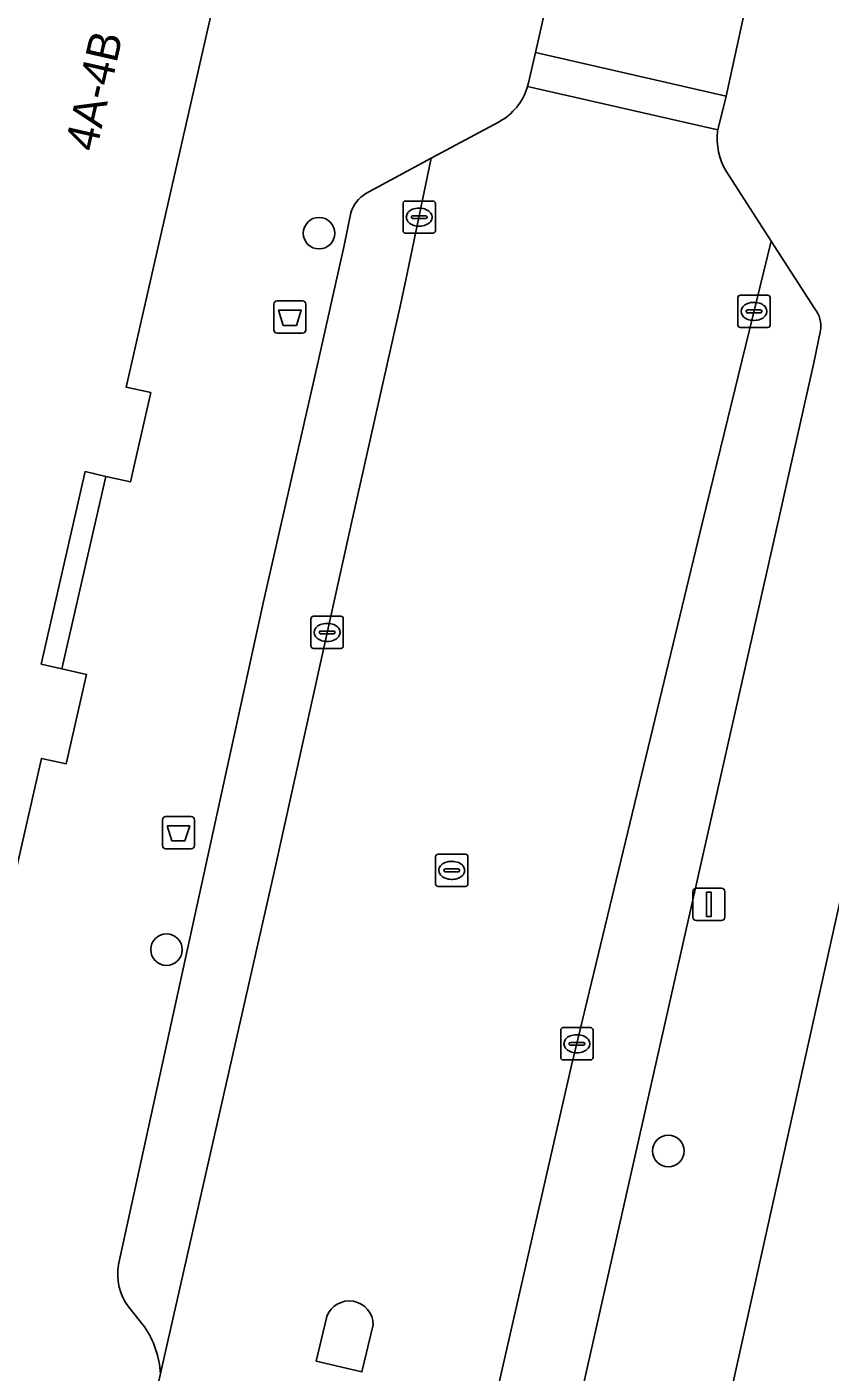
# Model space of a CAD drawing. Extents: x 161771 to 163125, y 382475 to 383179.
# Drawn here: x 162488.21 to 162513.11, y 382775.57 to 382817.29 of the extents above; entities that cross this region are included whole.
import ezdxf

# ---------------------------------------------------------------- set-up
doc = ezdxf.new("R2010")
doc.units = 0
for name, color, linetype in [('IMGEO_Afvalbak', 7, 'Continuous'), ('IMGEO_Boom', 7, 'Continuous'), ('IMGEO_Erf', 7, 'Continuous'), ('IMGEO_Kolk', 7, 'Continuous'), ('IMGEO_Lichtmast', 7, 'Continuous'), ('IMGEO_Pand', 7, 'Continuous'), ('IMGEO_Pand_nummerreeks', 7, 'Continuous'), ('IMGEO_Parkeervlak_open', 7, 'Continuous'), ('IMGEO_Rijbaan_lokaal_open', 7, 'Continuous'), ('IMGEO_Rioolput', 7, 'Continuous'), ('IMGEO_Verkeerseiland_gesloten', 7, 'Continuous'), ('IMGEO_Voetpad_open', 7, 'Continuous')]:
    doc.layers.add(name, color=color, linetype=linetype)

msp = doc.modelspace()

# ---------------------------------------------------------------- linework, layer by layer
at = {"layer": 'IMGEO_Afvalbak'}
for p, q in [((162495.868, 382807.886), (162495.868, 382808.686)), ((162495.868, 382808.686), (162495.868, 382807.886)), ((162495.968, 382808.786), (162496.758, 382808.786)), ((162496.758, 382808.786), (162495.968, 382808.786)), ((162496.858, 382808.686), (162496.858, 382807.886)), ((162496.858, 382807.886), (162496.858, 382808.686)), ((162496.758, 382807.786), (162495.968, 382807.786)), ((162495.968, 382807.786), (162496.758, 382807.786)), ((162492.414, 382791.895), (162492.414, 382792.695)), ((162492.414, 382792.695), (162492.414, 382791.895)), ((162492.514, 382792.795), (162493.304, 382792.795)), ((162493.304, 382792.795), (162492.514, 382792.795)), ((162493.404, 382792.695), (162493.404, 382791.895)), ((162493.404, 382791.895), (162493.404, 382792.695)), ((162493.304, 382791.795), (162492.514, 382791.795)), ((162492.514, 382791.795), (162493.304, 382791.795))]:
    msp.add_line(p, q, dxfattribs=at)
for points in [[(162496.011, 382808.5), (162496.715, 382808.5), (162496.566, 382808.03), (162496.16, 382808.03), (162496.011, 382808.5)], [(162492.557, 382792.509), (162493.261, 382792.509), (162493.112, 382792.039), (162492.706, 382792.039), (162492.557, 382792.509)]]:
    msp.add_lwpolyline(points, dxfattribs=at)
for centre, start, end in [((162495.968, 382808.686), 90, 180), ((162495.968, 382808.686), 90, 180), ((162496.758, 382808.686), 0, 90), ((162496.758, 382808.686), 360, 90), ((162495.968, 382807.886), 180, 270), ((162495.968, 382807.886), 180, 270), ((162496.758, 382807.886), 270, 0), ((162496.758, 382807.886), 270, 0), ((162492.514, 382792.695), 90, 180), ((162492.514, 382792.695), 90, 180), ((162493.304, 382792.695), 0, 90), ((162493.304, 382792.695), 360, 90), ((162492.514, 382791.895), 180, 270), ((162492.514, 382791.895), 180, 270), ((162493.304, 382791.895), 270, 0), ((162493.304, 382791.895), 270, 0)]:
    msp.add_arc(centre, 0.1, start, end, dxfattribs=at)
at = {"layer": 'IMGEO_Boom'}
for centre in [(162497.269, 382810.889), (162492.54, 382788.668), (162508.091, 382782.426)]:
    msp.add_circle(centre, 0.489, dxfattribs=at)
at = {"layer": 'IMGEO_Erf'}
msp.add_lwpolyline([(162516.107, 382774.679), (162516.72, 382777.452), (162517.354, 382780.316), (162516.872, 382780.422), (162517.638, 382783.886), (162518.434, 382787.483), (162518.947, 382787.369), (162519.547, 382790.08), (162520.181, 382792.947), (162519.663, 382793.062), (162520.436, 382796.553), (162521.242, 382800.197), (162521.832, 382800.066), (162522.427, 382802.759), (162523.068, 382805.656), (162522.524, 382805.776), (162523.312, 382809.334), (162523.399, 382809.647), (162524.848, 382809.317), (162526.114, 382815.089), (162519.291, 382816.631), (162509.13, 382770.881)], dxfattribs=at)
at = {"layer": 'IMGEO_Kolk'}
for p, q in [((162499.871, 382810.961), (162499.871, 382811.813)), ((162499.946, 382811.887), (162500.798, 382811.887)), ((162500.359, 382811.667), (162500.384, 382811.667)), ((162500.872, 382811.813), (162500.872, 382810.961)), ((162500.13, 382811.381), (162500.13, 382811.393)), ((162500.568, 382811.344), (162500.17, 382811.344)), ((162500.173, 382811.43), (162500.571, 382811.43)), ((162500.614, 382811.393), (162500.614, 382811.381)), ((162500.798, 382810.887), (162499.946, 382810.887)), ((162500.382, 382811.107), (162500.357, 382811.107)), ((162510.248, 382808.038), (162510.248, 382808.89)), ((162510.323, 382808.964), (162511.175, 382808.964)), ((162510.736, 382808.744), (162510.761, 382808.744)), ((162511.249, 382808.89), (162511.249, 382808.038)), ((162510.507, 382808.458), (162510.507, 382808.47)), ((162510.945, 382808.421), (162510.547, 382808.421)), ((162510.55, 382808.507), (162510.948, 382808.507)), ((162510.991, 382808.47), (162510.991, 382808.458)), ((162511.175, 382807.964), (162510.323, 382807.964)), ((162510.759, 382808.184), (162510.734, 382808.184)), ((162497.018, 382798.082), (162497.018, 382798.934)), ((162497.093, 382799.008), (162497.945, 382799.008)), ((162497.506, 382798.788), (162497.531, 382798.788)), ((162498.019, 382798.934), (162498.019, 382798.082)), ((162497.277, 382798.502), (162497.277, 382798.514)), ((162497.715, 382798.465), (162497.317, 382798.465)), ((162497.32, 382798.551), (162497.718, 382798.551)), ((162497.761, 382798.514), (162497.761, 382798.502)), ((162497.945, 382798.008), (162497.093, 382798.008)), ((162497.529, 382798.228), (162497.504, 382798.228)), ((162504.758, 382785.324), (162504.758, 382786.176)), ((162504.833, 382786.25), (162505.685, 382786.25)), ((162505.759, 382786.176), (162505.759, 382785.324)), ((162505.017, 382785.744), (162505.017, 382785.756)), ((162505.06, 382785.793), (162505.458, 382785.793)), ((162505.246, 382786.03), (162505.271, 382786.03)), ((162505.501, 382785.756), (162505.501, 382785.744)), ((162505.455, 382785.707), (162505.057, 382785.707)), ((162505.269, 382785.47), (162505.244, 382785.47)), ((162505.685, 382785.25), (162504.833, 382785.25))]:
    msp.add_line(p, q, dxfattribs=at)
for points in [[(162499.871, 382810.961), (162499.871, 382811.813)], [(162499.946, 382811.887), (162500.798, 382811.887)], [(162500.872, 382811.813), (162500.872, 382810.961)], [(162500.798, 382810.887), (162499.946, 382810.887)], [(162510.248, 382808.038), (162510.248, 382808.89)], [(162510.323, 382808.964), (162511.175, 382808.964)], [(162511.249, 382808.89), (162511.249, 382808.038)], [(162511.175, 382807.964), (162510.323, 382807.964)], [(162497.018, 382798.082), (162497.018, 382798.934)], [(162497.093, 382799.008), (162497.945, 382799.008)], [(162498.019, 382798.934), (162498.019, 382798.082)], [(162497.945, 382798.008), (162497.093, 382798.008)], [(162504.758, 382785.324), (162504.758, 382786.176)], [(162504.833, 382786.25), (162505.685, 382786.25)], [(162505.759, 382786.176), (162505.759, 382785.324)], [(162505.685, 382785.25), (162504.833, 382785.25)]]:
    msp.add_lwpolyline(points, dxfattribs=at)
for centre, radius, start, end in [((162499.948, 382811.811), 0.0765, 91.552, 178.448), ((162499.948, 382811.811), 0.0765, 91.552, 178.448), ((162500.796, 382811.811), 0.0765, 1.552, 88.448), ((162500.796, 382811.811), 0.0765, 1.552, 88.448), ((162500.17, 382811.39), 0.0403, 85.8775, 175.7526), ((162500.167, 382811.38), 0.0366, 178.938, 274.7102), ((162500.571, 382811.387), 0.043, 264.8664, 352.4533), ((162500.575, 382811.392), 0.0386, 1.7309, 96.639), ((162499.948, 382810.963), 0.0765, 181.552, 268.448), ((162499.948, 382810.963), 0.0765, 181.552, 268.448), ((162500.796, 382810.963), 0.0765, 271.552, 358.448), ((162500.796, 382810.963), 0.0765, 271.552, 358.448), ((162510.325, 382808.888), 0.0765, 91.552, 178.448), ((162510.325, 382808.888), 0.0765, 91.552, 178.448), ((162511.173, 382808.888), 0.0765, 1.552, 88.448), ((162511.173, 382808.888), 0.0765, 1.552, 88.448), ((162510.547, 382808.467), 0.0403, 85.8775, 175.7526), ((162510.544, 382808.457), 0.0366, 178.938, 274.7102), ((162510.948, 382808.464), 0.043, 264.8664, 352.4533), ((162510.952, 382808.469), 0.0386, 1.7309, 96.639), ((162510.325, 382808.04), 0.0765, 181.552, 268.448), ((162510.325, 382808.04), 0.0765, 181.552, 268.448), ((162511.173, 382808.04), 0.0765, 271.552, 358.448), ((162511.173, 382808.04), 0.0765, 271.552, 358.448), ((162497.095, 382798.932), 0.0765, 91.552, 178.448), ((162497.095, 382798.932), 0.0765, 91.552, 178.448), ((162497.943, 382798.932), 0.0765, 1.552, 88.448), ((162497.943, 382798.932), 0.0765, 1.552, 88.448), ((162497.317, 382798.511), 0.0403, 85.8775, 175.7526), ((162497.314, 382798.501), 0.0366, 178.938, 274.7102), ((162497.718, 382798.508), 0.043, 264.8664, 352.4533), ((162497.722, 382798.513), 0.0386, 1.7309, 96.639), ((162497.095, 382798.084), 0.0765, 181.552, 268.448), ((162497.095, 382798.084), 0.0765, 181.552, 268.448), ((162497.943, 382798.084), 0.0765, 271.552, 358.448), ((162497.943, 382798.084), 0.0765, 271.552, 358.448), ((162504.835, 382786.174), 0.0765, 91.552, 178.448), ((162504.835, 382786.174), 0.0765, 91.552, 178.448), ((162505.683, 382786.174), 0.0765, 1.552, 88.448), ((162505.683, 382786.174), 0.0765, 1.552, 88.448), ((162505.057, 382785.753), 0.0403, 85.8775, 175.7526), ((162505.054, 382785.743), 0.0366, 178.938, 274.7102), ((162505.458, 382785.75), 0.043, 264.8664, 352.4533), ((162505.462, 382785.755), 0.0386, 1.7309, 96.639), ((162504.835, 382785.326), 0.0765, 181.552, 268.448), ((162504.835, 382785.326), 0.0765, 181.552, 268.448), ((162505.683, 382785.326), 0.0765, 271.552, 358.448), ((162505.683, 382785.326), 0.0765, 271.552, 358.448)]:
    msp.add_arc(centre, radius, start, end, dxfattribs=at)
for centre, major_axis, ratio, start_param, end_param in [((162500.358, 382811.387), (-0.387, 0.002), 0.722429, 4.712389, 7.853982), ((162500.383, 382811.387), (-0.39, 0.002), 0.717154, 1.570796, 4.712389), ((162510.735, 382808.464), (-0.387, 0.002), 0.722429, 4.712389, 7.853982), ((162510.76, 382808.464), (-0.39, 0.002), 0.717154, 1.570796, 4.712389), ((162497.505, 382798.508), (-0.387, 0.002), 0.722429, 4.712389, 7.853982), ((162497.53, 382798.508), (-0.39, 0.002), 0.717154, 1.570796, 4.712389), ((162505.245, 382785.75), (-0.387, 0.002), 0.722429, 4.712389, 7.853982), ((162505.27, 382785.75), (-0.39, 0.002), 0.717154, 1.570796, 4.712389)]:
    msp.add_ellipse(centre, major_axis=major_axis, ratio=ratio, start_param=start_param, end_param=end_param, dxfattribs=at)
at = {"layer": 'IMGEO_Lichtmast'}
for p, q in [((162508.855, 382789.674), (162508.855, 382790.474)), ((162508.855, 382790.474), (162508.855, 382789.674)), ((162508.955, 382790.574), (162509.745, 382790.574)), ((162509.745, 382790.574), (162508.955, 382790.574)), ((162509.845, 382790.474), (162509.845, 382789.674)), ((162509.845, 382789.674), (162509.845, 382790.474)), ((162509.745, 382789.574), (162508.955, 382789.574)), ((162508.955, 382789.574), (162509.745, 382789.574))]:
    msp.add_line(p, q, dxfattribs=at)
msp.add_lwpolyline([(162509.275, 382790.449), (162509.425, 382790.449), (162509.425, 382789.699), (162509.275, 382789.699), (162509.275, 382790.449)], dxfattribs=at)
for centre, start, end in [((162508.955, 382790.474), 90, 180), ((162508.955, 382790.474), 90, 180), ((162509.745, 382790.474), 0, 90), ((162509.745, 382790.474), 360, 90), ((162508.955, 382789.674), 180, 270), ((162508.955, 382789.674), 180, 270), ((162509.745, 382789.674), 270, 0), ((162509.745, 382789.674), 270, 0)]:
    msp.add_arc(centre, 0.1, start, end, dxfattribs=at)
at = {"layer": 'IMGEO_Pand'}
msp.add_lwpolyline([(162484.441, 382776.066), (162488.665, 382794.601), (162489.427, 382794.428), (162490.06, 382797.207), (162489.299, 382797.38), (162488.656, 382797.527), (162490.016, 382803.494), (162490.658, 382803.348), (162491.42, 382803.174), (162492.051, 382805.943), (162491.289, 382806.116), (162494.91, 382822.004)], dxfattribs=at)
at = {"layer": 'IMGEO_Parkeervlak_open'}
for points in [[(162498.249, 382801.811), (162499.796, 382808.668), (162500, 382809.643), (162500.747, 382813.211), (162498.715, 382812.115)], [(162498.254, 382811.521), (162498.045, 382810.505), (162497.218, 382806.814), (162495.55, 382799.47), (162491.057, 382778.902)], [(162512.632, 382808.546), (162511.28, 382810.646), (162509.154, 382801.926), (162505.086, 382785.036), (162500.442, 382764.689), (162500, 382762.664), (162498.277, 382754.772), (162497.178, 382750), (162496.887, 382748.736), (162496.008, 382745.127), (162493.813, 382737.211), (162492.079, 382731.423), (162488.748, 382721.634), (162487.266, 382717.521), (162483.52, 382707.553), (162479.897, 382698.492), (162476.717, 382691.181), (162472.466, 382682.195), (162468.158, 382672.932), (162463.316, 382663.492), (162458.673, 382655.168), (162454.89, 382648.901), (162451.763, 382643.729), (162451.23, 382642.792)], [(162511.434, 382801.667), (162512.601, 382806.873), (162512.805, 382807.873)], [(162492.352, 382775.519), (162495.881, 382791.077), (162498.249, 382801.811)], [(162502.562, 382762.312), (162511.434, 382801.667)], [(162491.372, 382777.577), (162491.859, 382776.975)]]:
    msp.add_lwpolyline(points, dxfattribs=at)
for centre, radius, start, end in [((162499.234, 382811.237), 1.02, 120.5559, 163.8144), ((162511.994, 382808.023), 0.825, 349.5131, 39.3193), ((162492.695, 382778.591), 1.667, 169.2655, 217.4805), ((162489.461, 382775.352), 2.895, 3.3117, 34.1004)]:
    msp.add_arc(centre, radius, start, end, dxfattribs=at)
at = {"layer": 'IMGEO_Rijbaan_lokaal_open'}
for points in [[(162505.365, 382822.78), (162505.223, 382822.13), (162504.743, 382819.885), (162503.973, 382816.498), (162509.884, 382815.143), (162510.621, 382818.519), (162511.296, 382821.626), (162511.992, 382824.866)], [(162509.615, 382814.051), (162509.625, 382814.094), (162503.728, 382815.434)], [(162502.847, 382814.344), (162500.747, 382813.211), (162500, 382809.643), (162499.796, 382808.668), (162498.249, 382801.811), (162495.881, 382791.077), (162492.352, 382775.519), (162492.248, 382775.059), (162492.168, 382774.731), (162491.965, 382773.425), (162487.236, 382754.153), (162486.921, 382753.008), (162486.326, 382750.841), (162486.109, 382750), (162485.939, 382749.34), (162483.311, 382740.485), (162480.535, 382731.373)], [(162509.154, 382801.926), (162511.28, 382810.646), (162509.883, 382812.817)], [(162468.158, 382672.932), (162472.466, 382682.195), (162476.717, 382691.181), (162479.897, 382698.492), (162483.52, 382707.553), (162487.266, 382717.521), (162488.748, 382721.634), (162492.079, 382731.423), (162493.813, 382737.211), (162496.008, 382745.127), (162496.887, 382748.736), (162497.178, 382750), (162498.277, 382754.772), (162500, 382762.664), (162500.442, 382764.689), (162505.086, 382785.036), (162509.154, 382801.926)], [(162498.596, 382775.571), (162497.178, 382775.911), (162497.508, 382777.289)], [(162498.948, 382777.038), (162498.596, 382775.571)]]:
    msp.add_lwpolyline(points, dxfattribs=at)
msp.add_lwpolyline([(162503.973, 382816.498), (162503.758, 382815.55), (162503.728, 382815.434), (162509.625, 382814.094), (162509.884, 382815.143)], close=True, dxfattribs=at)
for centre, radius, start, end in [((162501.973, 382815.952), 1.83, 298.5364, 343.5694), ((162511.646, 382813.846), 2.041, 174.2369, 210.2695), ((162498.205, 382777.032), 0.743, 0.469, 159.7558)]:
    msp.add_arc(centre, radius, start, end, dxfattribs=at)
at = {"layer": 'IMGEO_Rioolput'}
for p, q in [((162500.956, 382791.628), (162501.808, 382791.628)), ((162500.881, 382790.702), (162500.881, 382791.554)), ((162501.183, 382791.171), (162501.581, 382791.171)), ((162501.369, 382791.408), (162501.394, 382791.408)), ((162501.882, 382791.554), (162501.882, 382790.702)), ((162501.14, 382791.122), (162501.14, 382791.134)), ((162501.578, 382791.085), (162501.18, 382791.085)), ((162501.392, 382790.848), (162501.367, 382790.848)), ((162501.624, 382791.134), (162501.624, 382791.122)), ((162501.808, 382790.628), (162500.956, 382790.628))]:
    msp.add_line(p, q, dxfattribs=at)
for points in [[(162500.956, 382791.628), (162501.808, 382791.628)], [(162500.881, 382790.702), (162500.881, 382791.554)], [(162501.882, 382791.554), (162501.882, 382790.702)], [(162501.808, 382790.628), (162500.956, 382790.628)]]:
    msp.add_lwpolyline(points, dxfattribs=at)
for centre, radius, start, end in [((162500.958, 382791.552), 0.0765, 91.552, 178.448), ((162500.958, 382791.552), 0.0765, 91.552, 178.448), ((162501.806, 382791.552), 0.0765, 1.552, 88.448), ((162501.806, 382791.552), 0.0765, 1.552, 88.448), ((162501.18, 382791.131), 0.0403, 85.8775, 175.7526), ((162501.585, 382791.133), 0.0386, 1.7309, 96.639), ((162501.177, 382791.121), 0.0366, 178.938, 274.7102), ((162501.581, 382791.128), 0.043, 264.8664, 352.4533), ((162500.958, 382790.704), 0.0765, 181.552, 268.448), ((162500.958, 382790.704), 0.0765, 181.552, 268.448), ((162501.806, 382790.704), 0.0765, 271.552, 358.448), ((162501.806, 382790.704), 0.0765, 271.552, 358.448)]:
    msp.add_arc(centre, radius, start, end, dxfattribs=at)
for centre, major_axis, ratio, start_param, end_param in [((162501.368, 382791.128), (-0.387, 0.002), 0.722429, 4.712389, 7.853982), ((162501.393, 382791.128), (-0.39, 0.002), 0.717154, 1.570796, 4.712389)]:
    msp.add_ellipse(centre, major_axis=major_axis, ratio=ratio, start_param=start_param, end_param=end_param, dxfattribs=at)
at = {"layer": 'IMGEO_Verkeerseiland_gesloten'}
msp.add_lwpolyline([(162497.508, 382777.289), (162497.178, 382775.911), (162498.596, 382775.571), (162498.948, 382777.038)], dxfattribs=at)
msp.add_arc((162498.205, 382777.032), 0.743, 0.469, 159.7558, dxfattribs=at)
at = {"layer": 'IMGEO_Voetpad_open'}
for points in [[(162503.728, 382815.434), (162503.758, 382815.55), (162503.973, 382816.498), (162504.743, 382819.885), (162494.91, 382822.004), (162491.289, 382806.116), (162492.051, 382805.943), (162491.42, 382803.174), (162490.658, 382803.348), (162489.299, 382797.38), (162490.06, 382797.207), (162489.427, 382794.428), (162488.665, 382794.601), (162484.441, 382776.066), (162483.267, 382770.618), (162485.023, 382770.227)], [(162519.291, 382816.631), (162510.621, 382818.519), (162509.884, 382815.143), (162509.625, 382814.094), (162509.615, 382814.051)], [(162472.565, 382660.277), (162467.218, 382645.531), (162463.814, 382636.141), (162468.305, 382634.573), (162489.16, 382693.298), (162492.061, 382702.197), (162492.531, 382703.794), (162496.253, 382716.455), (162500, 382730.308), (162503.472, 382745.528), (162503.806, 382746.991), (162504.492, 382750), (162508.826, 382769.514), (162509.13, 382770.881), (162519.291, 382816.631)], [(162498.715, 382812.115), (162500.747, 382813.211), (162502.847, 382814.344)], [(162509.883, 382812.817), (162511.28, 382810.646), (162512.632, 382808.546)], [(162495.55, 382799.47), (162497.218, 382806.814), (162498.045, 382810.505), (162498.254, 382811.521)], [(162512.805, 382807.873), (162512.601, 382806.873), (162511.434, 382801.667), (162502.562, 382762.312)], [(162491.057, 382778.902), (162495.55, 382799.47)], [(162491.859, 382776.975), (162491.372, 382777.577)]]:
    msp.add_lwpolyline(points, dxfattribs=at)
msp.add_lwpolyline([(162490.016, 382803.494), (162488.656, 382797.527), (162489.299, 382797.38), (162490.658, 382803.348)], close=True, dxfattribs=at)
for centre, radius, start, end in [((162501.973, 382815.952), 1.83, 298.5364, 343.5694), ((162511.646, 382813.846), 2.041, 174.2369, 210.2695), ((162499.234, 382811.237), 1.02, 120.5559, 163.8144), ((162511.994, 382808.023), 0.825, 349.5131, 39.3193), ((162492.695, 382778.591), 1.667, 169.2655, 217.4805), ((162489.461, 382775.352), 2.895, 3.3117, 34.1004)]:
    msp.add_arc(centre, radius, start, end, dxfattribs=at)

# ---------------------------------------------------------------- texts
at = {"layer": 'IMGEO_Pand_nummerreeks'}
msp.add_text('4A-4B', height=1, rotation=77.1602, dxfattribs=at).set_placement((162490.362, 382813.385))

doc.saveas('drawing.dxf')
